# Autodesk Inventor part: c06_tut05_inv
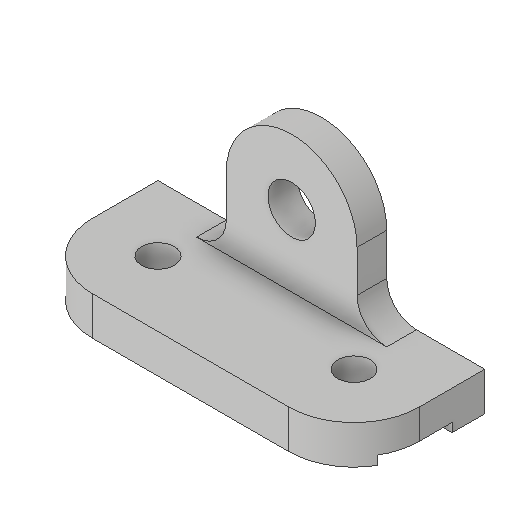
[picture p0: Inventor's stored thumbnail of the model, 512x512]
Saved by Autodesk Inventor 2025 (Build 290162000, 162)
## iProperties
Created: 2015-03
Part Number: c06_tut05_inv
Material: Generic
Document SubType Name: Modeling
Designer: Sandeep
Density: 1 g/cm^3
Appearance: Default
Author: Sandeep
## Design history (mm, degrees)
sketch "Sketch1"
  geometry: L1 (-11, 0)-(11, 0); L2 (11, 0)-(11, -3); L3 (11, -3)-(22, -3); L4 (22, -3)-(22, 10); L5 (22, 10)-(-22, 10); L6 (-22, 10)-(-22, -3); L7 (-22, -3)-(-11, -3); L8 (-11, -3)-(-11, 0); L9 (0, 13.216)-(0, -4.005); 2 further points
  constraints: 18 end point, 6 perpendicular, 4 point on line, 2 midpoint, 1 horizontal, 1 vertical, 1 other
  dimensions: "d0" = 22 distance of L1.start L1.end; "d1" = 44 distance of L4.end L5.end; "d2" = 3 distance between parallel lines of L1 L3; "d3" = 13 distance between parallel lines of L5 L3
extrude "Extrusion1" new body sketch "Sketch1" stored distance "d4" = 110; taper "d5" = 0 deg
fillet "Fillet1" dims "d6" = 22
mirror "Mirror1"
sketch "Sketch2"
  geometry: L1 (22, 0)-(88, 0) reference; L2 (77, 0)-(77, -24); L3 (33, -24)-(33, 0); L4 (77, 0)-(33, 0); L5 (0, 13)-(110, 13) reference; L6 (0, 0)-(0, 13) reference; C1 r 8 at (55, -24); A1 r 22 centre (55, -24) between (33, -24) and (77, -24); 1 further point
  constraints: 6 end point, 2 centre point, 2 point on circle, 2 point on line, 2 tangent, 1 coincident, 1 collinear, 1 parallel, 1 vertical
  dimensions: "d7" = 22 radius of A1; "d8" = 37 distance from line of L5 A1.centre; "d9" = 55 distance from line of L6 A1.centre; "d23" = 16 diameter of C1
extrude "Extrusion2" join sketch "Sketch2" distance "d11" = 10; taper "d12" = 0 deg
fillet "Fillet2" dims "d13" = 10
mirror "Mirror2"
hole "Hole1" diameter "d16" = 11; stored, may be unused: countersink angle "d20" = 90 deg, drill point angle "d22" = 118 deg; dims "d14" = 10, "d15" = 10, "d17" = 6, "d18" = 4, "d19" = 2, "d21" = 8
mirror "Mirror3"
body "Solid1"
